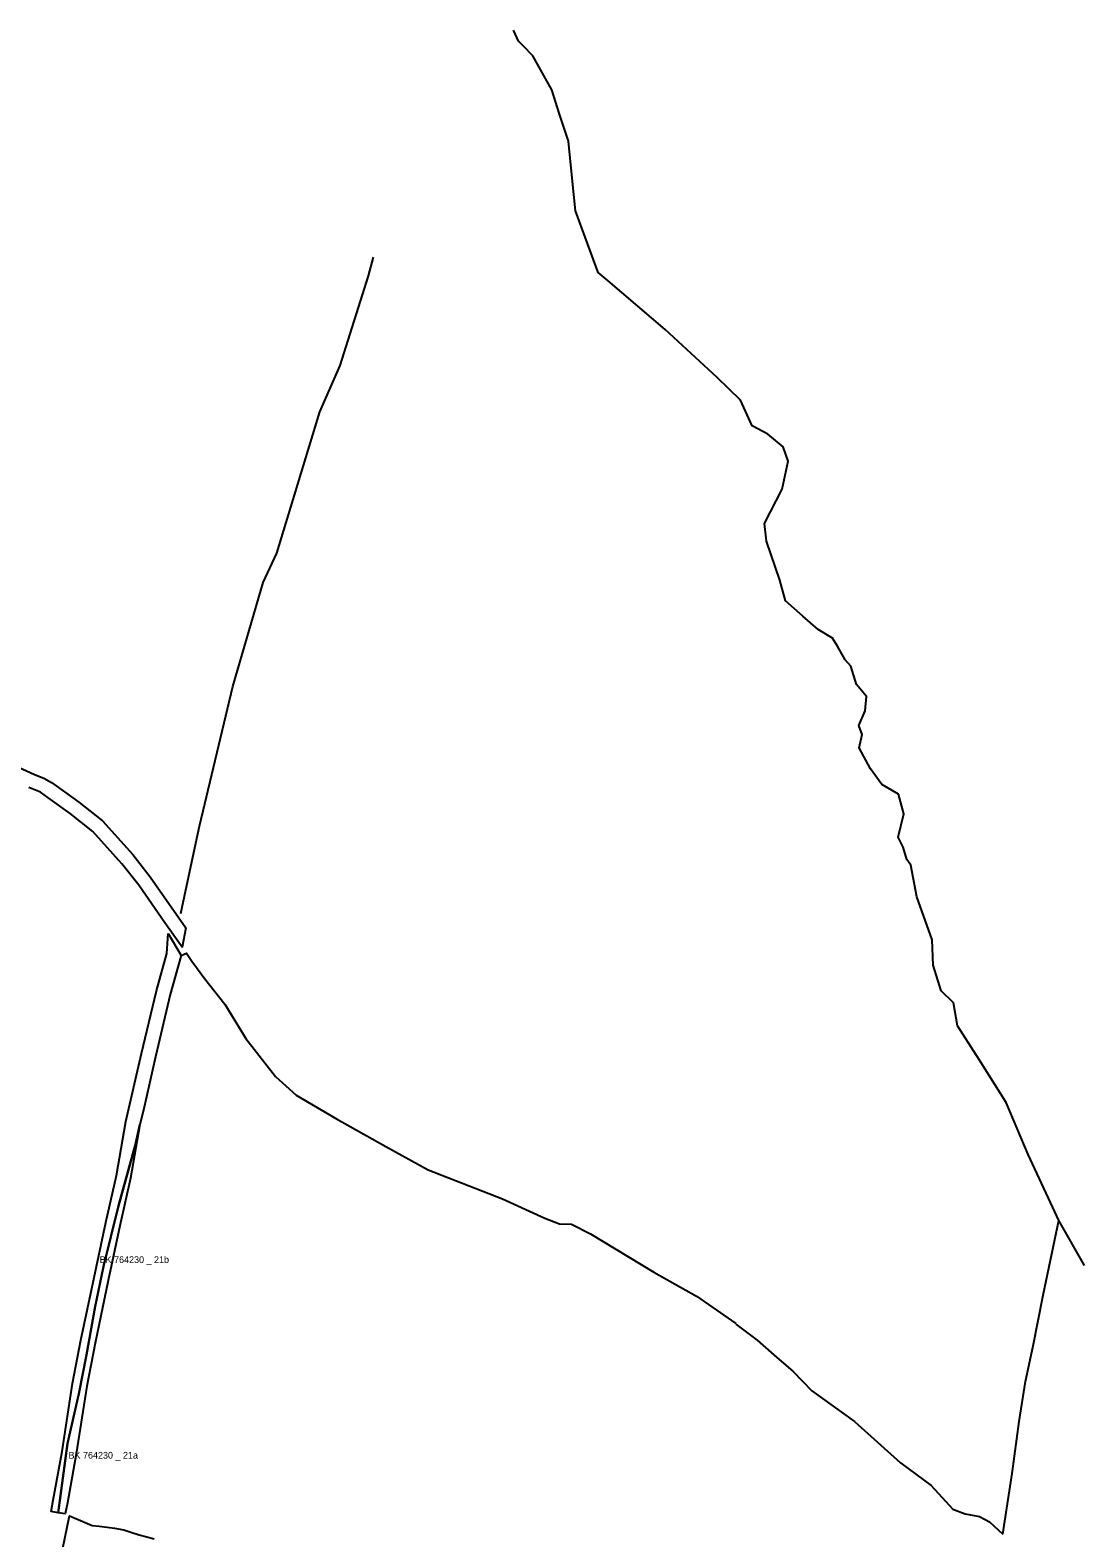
# Model space of a CAD drawing. Extents: x -521616 to -516782, y -1190061 to -1184927.
# Drawn here: x -520537 to -519440, y -1188996 to -1187424 of the extents above; entities that cross this region are included whole.
import ezdxf

# ---------------------------------------------------------------- set-up
doc = ezdxf.new("R2010")
doc.units = 0
for name, color, linetype in [('i_prvek_l_n', 7, 'Continuous'), ('i_prvek_l_s', 7, 'Continuous'), ('LBC_s', 7, 'Continuous'), ('LBK_n', 7, 'Continuous'), ('LBK_s', 7, 'Continuous')]:
    doc.layers.add(name, color=color, linetype=linetype)

msp = doc.modelspace()

# ---------------------------------------------------------------- linework, layer by layer
at = {"layer": 'i_prvek_l_n'}
for points in [[(-519438.2, -1188712.2), (-519464.9, -1188665.5), (-519471.2, -1188651.7), (-519496.8, -1188596.4), (-519519.9, -1188542.5), (-519547.8, -1188498.1), (-519570.5, -1188462.6), (-519574.7, -1188438.3), (-519587.7, -1188425.8), (-519596.1, -1188399.1), (-519597.1, -1188372.8), (-519613, -1188327.8), (-519619.1, -1188295), (-519623.3, -1188289), (-519627.1, -1188276.2), (-519632.4, -1188265.8), (-519626.4, -1188241.3), (-519632.2, -1188220.8), (-519649.4, -1188210.8), (-519661.3, -1188194.4), (-519673.1, -1188172.7), (-519670.1, -1188158.8), (-519673.5, -1188149.5), (-519666.7, -1188133.9), (-519665.5, -1188119.1), (-519675.7, -1188106.7), (-519681.8, -1188087.4), (-519687.8, -1188080.9), (-519695.7, -1188066.7), (-519700.7, -1188058.2), (-519715.8, -1188049.2), (-519731.6, -1188035.5), (-519750, -1188019.4), (-519755.8, -1187997.8), (-519769.7, -1187957.1), (-519771.6, -1187938.7), (-519753.4, -1187903.1), (-519747.1, -1187873.8), (-519752.4, -1187858.8), (-519768.2, -1187845.7), (-519784.7, -1187837), (-519796.9, -1187810.2), (-519821.2, -1187786.7), (-519875.1, -1187736.4), (-519934.8, -1187685.7), (-519944.9, -1187677.2), (-519956.1, -1187646.7), (-519968.5, -1187612.8), (-519972.2, -1187578.6), (-519976, -1187540.1), (-519985.5, -1187511.9), (-519993.2, -1187486.8), (-520013.3, -1187451.3), (-520022.9, -1187441.2), (-520027.9, -1187435.9), (-520033.3, -1187424.5)], [(-520380, -1188345.2), (-520374.8, -1188320.8), (-520360.5, -1188254.4), (-520325.7, -1188108.6), (-520294.3, -1188000.2), (-520280, -1187969.8), (-520235.2, -1187822.5), (-520213.9, -1187774.2), (-520184.5, -1187680.6), (-520179.3, -1187661.2)], [(-520379.5, -1188389.1), (-520374.2, -1188386.8), (-520368.4, -1188394.9), (-520355, -1188413.5), (-520334, -1188439.9), (-520312.1, -1188475.8), (-520281.4, -1188515.3), (-520259.8, -1188534.6), (-520217.8, -1188559.3), (-520166.2, -1188588.2), (-520122.3, -1188612.4), (-520044.8, -1188642.9), (-520000.5, -1188662.8), (-519985.5, -1188669), (-519972.8, -1188669.2), (-519953, -1188679.1), (-519887.2, -1188719.3), (-519842.5, -1188744.3), (-519801.6, -1188772.7)]]:
    msp.add_lwpolyline(points, dxfattribs=at)
at = {"layer": 'i_prvek_l_s'}
for points in [[(-519523.3, -1188992.5), (-519513.7, -1188929.1), (-519506.3, -1188874.9), (-519499.7, -1188833.1), (-519491.9, -1188796), (-519481.3, -1188743.2), (-519469.2, -1188685.1), (-519464.9, -1188665.5)], [(-519801.6, -1188773.4), (-519779.2, -1188790.1), (-519758.8, -1188808.1), (-519742.2, -1188822.4), (-519722.5, -1188843.1), (-519678, -1188874.9), (-519630, -1188917.9), (-519598, -1188941.6), (-519575.6, -1188966.4), (-519562.5, -1188971), (-519547.6, -1188974), (-519537.2, -1188979.4), (-519523.3, -1188992.5)]]:
    msp.add_lwpolyline(points, dxfattribs=at)
at = {"layer": 'LBC_s'}
msp.add_lwpolyline([(-520502.9, -1189007.1), (-520496.1, -1188973.2), (-520482.1, -1188979.1), (-520472.5, -1188983.2), (-520465.1, -1188984.1), (-520456.6, -1188985.1), (-520448.9, -1188986), (-520439.5, -1188988), (-520431.9, -1188990.3), (-520423.4, -1188992.9), (-520415.3, -1188995.2), (-520407.7, -1188997.2)], dxfattribs=at)
at = {"layer": 'LBK_n'}
msp.add_lwpolyline([(-520552.9, -1188191.1), (-520532.3, -1188200.3), (-520522.7, -1188204.2), (-520514.6, -1188208.8), (-520509.7, -1188212.3), (-520486.1, -1188229.3), (-520461.5, -1188248.8), (-520429.9, -1188283.9), (-520411.8, -1188307), (-520374.8, -1188360.1), (-520378.7, -1188380.4), (-520396.5, -1188355.1), (-520423.8, -1188315.9), (-520441.4, -1188293.5), (-520471.8, -1188259.7), (-520495.1, -1188241.2), (-520518.5, -1188224.5), (-520526.1, -1188219), (-520538.2, -1188214.1)], dxfattribs=at)
msp.add_lwpolyline([(-520393.3, -1188366.1), (-520379.5, -1188389.1), (-520379.8, -1188390), (-520390.9, -1188429.8), (-520406.4, -1188494.8), (-520419, -1188550.3), (-520422.5, -1188565.2), (-520427.5, -1188587.1), (-520444.8, -1188650.2), (-520460.4, -1188713.3), (-520469.2, -1188755), (-520478.3, -1188805.3), (-520486.3, -1188845.9), (-520498.2, -1188898), (-520507.9, -1188970.2), (-520515.2, -1188968.8), (-520512.9, -1188957), (-520503.7, -1188906.2), (-520492.7, -1188835.4), (-520484, -1188790.1), (-520470.4, -1188724.9), (-520458.1, -1188667.6), (-520447, -1188618.5), (-520437.2, -1188562.2), (-520421, -1188491.4), (-520405.4, -1188426), (-520394.5, -1188387.2)], close=True, dxfattribs=at)
at = {"layer": 'LBK_s'}
msp.add_lwpolyline([(-520422.5, -1188565.2), (-520432.3, -1188621.4), (-520443.5, -1188670.9), (-520455.7, -1188728), (-520469.3, -1188793.1), (-520477.9, -1188838), (-520488.9, -1188908.7), (-520498.1, -1188959.8), (-520500.4, -1188971), (-520507.9, -1188970.2), (-520498.2, -1188898), (-520486.3, -1188845.9), (-520478.3, -1188805.3), (-520469.2, -1188755), (-520460.4, -1188713.3), (-520444.8, -1188650.2), (-520427.5, -1188587.1)], close=True, dxfattribs=at)

# ---------------------------------------------------------------- texts
at = {"layer": 'LBK_n'}
msp.add_text('BK 764230 _ 21b', height=7, dxfattribs=at).set_placement((-520464.6, -1188709.7))
at = {"layer": 'LBK_s'}
msp.add_text('BK 764230 _ 21a', height=7, dxfattribs=at).set_placement((-520497, -1188913.6))

doc.saveas('drawing.dxf')
